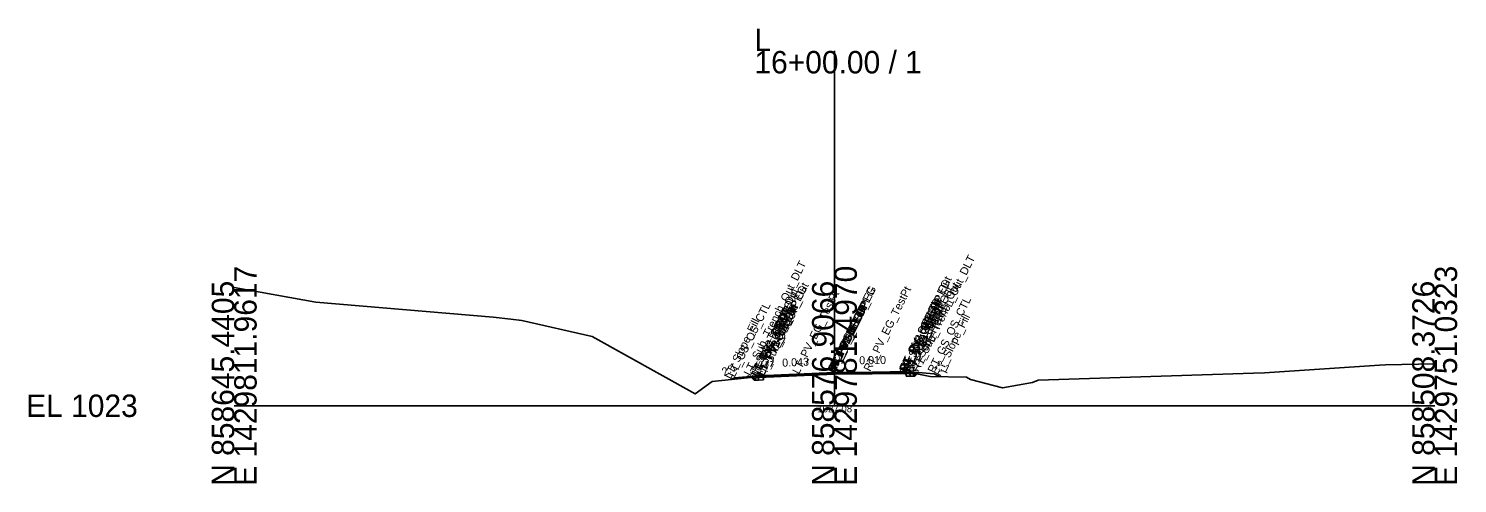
# Model space of a CAD drawing. Extents: x -26 to 153, y -10 to 13058.
# Drawn here: x -25.7 to 152.8, y 8990.3 to 9047.1 of the extents above; entities that cross this region are included whole.
import ezdxf

# ---------------------------------------------------------------- set-up
doc = ezdxf.new("R2010")
doc.units = 0
for name, color, linetype in [('Default', 7, 'Continuous'), ('Exist Cross Section Cell', 7, 'Continuous'), ('Exist XS Ground Line', 7, 'Continuous'), ('Prop CMT Pvmt Course 1', 7, 'Continuous'), ('Prop CMT Pvmt Course 2', 7, 'Continuous'), ('Prop CMT Pvmt Surface', 7, 'Continuous'), ('Prop CMT Pvmt Surface Shoulder', 7, 'Continuous'), ('Prop CMT Pvmt Wedge Surface 1', 7, 'Continuous'), ('Prop CMT Pvmt Wedge Surface 2', 7, 'Continuous'), ('Prop CMT Shld Paved Course 1', 7, 'Continuous'), ('Prop CMT Shld Paved Course 2', 7, 'Continuous'), ('Prop CMT Slope Grass', 7, 'Continuous'), ('Prop CMT Subgrade Daylight Point', 7, 'Continuous'), ('Prop CMT Subgrade Earthwork', 7, 'Continuous'), ('Prop XS Dump Level', 7, 'Continuous'), ('Prop XS SE Text', 7, 'Continuous'), ('Prop XS Side Slope Text', 7, 'Continuous')]:
    doc.layers.add(name, color=color, linetype=linetype)

msp = doc.modelspace()

# ---------------------------------------------------------------- linework, layer by layer
at = {"layer": 'Exist Cross Section Cell'}
for p, q in [((75, 9000), (75, 9044.29)), ((0, 9000), (75, 9000)), ((75, 9000), (150, 9000))]:
    msp.add_line(p, q, dxfattribs=at)
at = {"layer": 'Exist XS Ground Line'}
msp.add_lwpolyline([(0, 9014.76), (10.21, 9012.94), (32.34, 9011.06), (34.57, 9010.83), (35.92, 9010.64), (44.71, 9008.63), (57.6, 9001.47), (59.73, 9003.02), (64.15, 9003.48), (66.08, 9003.68), (66.71, 9003.71), (74.78, 9004.07), (80.07, 9004.21), (83.79, 9004.29), (86.98, 9003.64), (91.49, 9003.55), (92, 9003.27), (96, 9002.24), (99.74, 9002.91), (100.44, 9003.21), (127.34, 9004.06), (128.73, 9004.11), (143.09, 9005.08), (143.86, 9005.12), (150, 9005.25)], dxfattribs=at)
at = {"layer": 'Prop CMT Pvmt Course 1'}
for points in [[(75, 9004.15), (65.53, 9003.74)], [(65.53, 9003.74), (65.53, 9003.53)], [(65.53, 9003.53), (66.14, 9003.56)], [(66.14, 9003.64), (75, 9004.02)], [(66.14, 9003.56), (66.14, 9003.64)], [(75, 9004.15), (84.48, 9004.24)], [(75, 9003.94), (75, 9004.15)], [(75, 9003.94), (75, 9004.15)], [(83.95, 9004.11), (75, 9004.02)], [(75, 9004.02), (75, 9003.94), (75, 9003.94)], [(75, 9004.02), (75, 9003.94), (75, 9003.94)], [(83.95, 9004.03), (83.95, 9004.11)], [(84.48, 9004.03), (83.95, 9004.03)], [(84.48, 9004.24), (84.48, 9004.03)]]:
    msp.add_lwpolyline(points, dxfattribs=at)
at = {"layer": 'Prop CMT Pvmt Course 2'}
for points in [[(66.14, 9003.56), (65.53, 9003.53)], [(65.53, 9003.53), (65.53, 9003.2)], [(66.14, 9003.23), (66.14, 9003.56)], [(83.95, 9003.69), (83.95, 9004.03)], [(83.95, 9004.03), (84.48, 9004.03)], [(84.48, 9003.7), (83.95, 9003.69)], [(84.48, 9004.03), (84.48, 9003.7)], [(65.53, 9003.2), (66.14, 9003.23)]]:
    msp.add_lwpolyline(points, dxfattribs=at)
at = {"layer": 'Prop CMT Pvmt Surface'}
for points in [[(75, 9004.15), (65.53, 9003.74)], [(75, 9004.15), (84.48, 9004.24)]]:
    msp.add_lwpolyline(points, dxfattribs=at)
at = {"layer": 'Prop CMT Pvmt Surface Shoulder'}
for points in [[(65.53, 9003.74), (65.53, 9003.74)], [(84.48, 9004.24), (84.48, 9004.24)]]:
    msp.add_lwpolyline(points, dxfattribs=at)
at = {"layer": 'Prop CMT Pvmt Wedge Surface 1'}
for points in [[(65.53, 9003.53), (65.53, 9003.74)], [(66.14, 9003.56), (65.53, 9003.53)], [(75, 9004.02), (66.14, 9003.64)], [(66.14, 9003.64), (66.14, 9003.56)], [(75, 9004.02), (83.95, 9004.11)], [(83.95, 9004.11), (83.95, 9004.03)], [(83.95, 9004.03), (84.48, 9004.03)], [(84.48, 9004.03), (84.48, 9004.24)]]:
    msp.add_lwpolyline(points, dxfattribs=at)
at = {"layer": 'Prop CMT Pvmt Wedge Surface 2'}
for points in [[(75, 9003.94), (65.53, 9003.53)], [(65.53, 9003.53), (65.53, 9003.74)], [(75, 9003.94), (84.48, 9004.03)], [(84.48, 9004.03), (84.48, 9004.24)]]:
    msp.add_lwpolyline(points, dxfattribs=at)
at = {"layer": 'Prop CMT Shld Paved Course 1'}
for points in [[(65.53, 9003.74), (65.31, 9003.53)], [(65.31, 9003.53), (65.53, 9003.53)], [(65.53, 9003.74), (65.53, 9003.74)], [(65.53, 9003.53), (65.53, 9003.74)], [(84.48, 9004.24), (84.48, 9004.24)], [(84.48, 9004.24), (84.69, 9004.03)], [(84.48, 9004.03), (84.48, 9004.24)], [(84.69, 9004.03), (84.48, 9004.03)]]:
    msp.add_lwpolyline(points, dxfattribs=at)
at = {"layer": 'Prop CMT Shld Paved Course 2'}
for points in [[(65.31, 9003.53), (64.97, 9003.19)], [(65.53, 9003.53), (65.31, 9003.53)], [(65.31, 9003.53), (65.31, 9003.53)], [(65.53, 9003.2), (65.53, 9003.53)], [(84.48, 9004.03), (84.69, 9004.03)], [(84.48, 9003.7), (84.48, 9004.03)], [(85.03, 9003.69), (84.48, 9003.7)], [(84.69, 9004.03), (84.69, 9004.03)], [(84.69, 9004.03), (85.03, 9003.69)], [(64.97, 9003.19), (65.53, 9003.2)]]:
    msp.add_lwpolyline(points, dxfattribs=at)
at = {"layer": 'Prop CMT Slope Grass'}
for points in [[(65.53, 9003.74), (62.53, 9003.5), (62.04, 9003.26)], [(84.48, 9004.24), (87.48, 9004), (88.25, 9003.62)]]:
    msp.add_lwpolyline(points, dxfattribs=at)
at = {"layer": 'Prop CMT Subgrade Earthwork'}
for points in [[(64.97, 9003.19), (64.5, 9003.66)], [(66.14, 9003.23), (66.16, 9003.68)], [(83.95, 9003.69), (83.93, 9004.26)], [(83.95, 9003.69), (84.48, 9003.7)], [(84.48, 9003.7), (85.03, 9003.69)], [(85.03, 9003.69), (85.5, 9004.16)], [(65.53, 9003.2), (64.97, 9003.19)], [(66.14, 9003.23), (65.53, 9003.2)]]:
    msp.add_lwpolyline(points, dxfattribs=at)

# ---------------------------------------------------------------- texts
at = {"layer": 'Default'}
msp.add_text('-', height=0.0001, dxfattribs=at).set_placement((0, 9000))
at = {"layer": 'Exist Cross Section Cell'}
for s, p in [('L', (65, 9044.29)), ('16+00.00 / 1', (65, 9041.49)), ('EL 1023', (-26, 8998.6))]:
    msp.add_text(s, height=2.8, dxfattribs=at).set_placement(p)
for s, p in [('E 1429811.9617', (2.8, 8990)), ('E 1429781.4970', (77.8, 8990)), ('E 1429751.0323', (152.8, 8990)), ('N 858645.4405', (0, 8990)), ('N 858576.9066', (75, 8990)), ('N 858508.3726', (150, 8990))]:
    msp.add_text(s, height=2.8, rotation=90, dxfattribs=at).set_placement(p)
at = {"layer": 'Prop CMT Subgrade Daylight Point'}
msp.add_text('1027.08', height=0.9, dxfattribs=at).set_placement((72.86, 8999.18))
at = {"layer": 'Prop XS Dump Level'}
for s, p in [('LT_Sub_Trench_Out_DLT', (64.5, 9003.66)), ('RT_Sub_Trench_Out_DLT', (85.5, 9004.16)), ('RT_PV_Sub_Tie_Out', (83.93, 9004.26)), ('LT_Sub_Trench_Out', (64.97, 9003.19)), ('LT_PS2_Shelf_Out', (65.31, 9003.53)), ('LT_PV_OEEOP_EG', (66.14, 9003.68)), ('LT_PV_Sub_Tie_Out', (66.16, 9003.68)), ('LT_PV_EG_TestPt', (70.57, 9003.88)), ('RT_PV_IEEOP_EG', (75, 9004.08)), ('LT_PV_IEEOP_EG', (75, 9004.08)), ('RT_PV_EG_TestPt', (79.47, 9004.2)), ('RT_PV_OEEOP_EG', (83.95, 9004.26)), ('RT_PS2_Shelf_Out', (84.69, 9004.03)), ('RT_Sub_Trench_Out', (85.03, 9003.69)), ('LT_GS_OS_CTL', (62.53, 9003.5)), ('LT_PV1_OEOT', (65.53, 9003.74)), ('LT_PS1_OEOP', (65.53, 9003.74)), ('LT_PV2_OEOT', (65.53, 9003.53)), ('LT_PV1_OEEOP', (66.14, 9003.64)), ('LT_PV2_OEEOP', (66.14, 9003.56)), ('LT_Sub_OEEOP', (66.14, 9003.23)), ('RT_PV1_IEEOP', (75, 9004.02)), ('RT_PV2_IEEOP', (75, 9003.94)), ('LT_PV1_IEEOP', (75, 9004.02)), ('LT_PV2_IEEOP', (75, 9003.94)), ('RT_PV1_OEEOP', (83.95, 9004.11)), ('RT_PV2_OEEOP', (83.95, 9004.03)), ('RT_Sub_OEEOP', (83.95, 9003.69)), ('RT_PV1_OEOT', (84.48, 9004.24)), ('RT_PS1_OEOP', (84.48, 9004.24)), ('RT_PV2_OEOT', (84.48, 9004.03)), ('RT_Sub_OEOT', (84.48, 9003.7)), ('RT_PS2_OEOP', (84.69, 9004.03)), ('RT_GS_OS_CTL', (87.48, 9004)), ('LT_Slope_Fill', (62.04, 9003.26)), ('LT_PS2_OEOP', (65.31, 9003.53)), ('LT_Sub_OEOT', (65.53, 9003.2)), ('RT_Slope_Fill', (88.25, 9003.62)), ('PV1_PGL', (75, 9004.15)), ('PV2_PGL', (75, 9003.94))]:
    msp.add_text(s, height=1, rotation=63.5833, dxfattribs=at).set_placement(p)
at = {"layer": 'Prop XS SE Text'}
for s, rotation, p in [('0.043', 2.4431, (68.49, 9004.87)), ('0.010', 0.5729, (78.1, 9005.18))]:
    msp.add_text(s, height=1, rotation=rotation, dxfattribs=at).set_placement(p)
at = {"layer": 'Prop XS Side Slope Text'}
for rotation, p in [(26.5651, (61.24, 9003.7)), (333.4349, (87.49, 9004.83))]:
    msp.add_text('2:1', height=1, rotation=rotation, dxfattribs=at).set_placement(p)

doc.saveas('drawing.dxf')
